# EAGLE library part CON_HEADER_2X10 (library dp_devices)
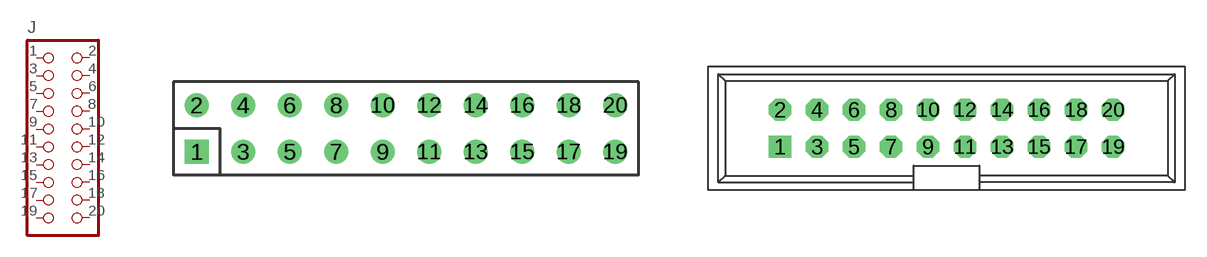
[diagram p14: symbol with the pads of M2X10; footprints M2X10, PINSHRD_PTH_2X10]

Designator prefix J

## CON_HEADER_2X10-PTH  [M2X10]
1  1  pas
2  2  pas
3  3  pas
4  4  pas
5  5  pas
6  6  pas
7  7  pas
8  8  pas
9  9  pas
10  10  pas
11  11  pas
12  12  pas
13  13  pas
14  14  pas
15  15  pas
16  16  pas
17  17  pas
18  18  pas
19  19  pas
20  20  pas

## CON_HEADER_2X10-SHROUDED  [PINSHRD_PTH_2X10]
Pads as for M2X10

## Footprint M2X10 (pad centres in mm)
drill 0.8 square: 1 -11.43,-1.27
drill 0.8 round: 2 -11.43,1.27; 3 -8.89,-1.27; 4 -8.89,1.27; 5 -6.35,-1.27; 6 -6.35,1.27; 7 -3.81,-1.27; 8 -3.81,1.27; 9 -1.27,-1.27; 10 -1.27,1.27; 11 1.27,-1.27; 12 1.27,1.27; 13 3.81,-1.27; 14 3.81,1.27; 15 6.35,-1.27; 16 6.35,1.27; 17 8.89,-1.27; 18 8.89,1.27; 19 11.43,-1.27; 20 11.43,1.27

## Footprint PINSHRD_PTH_2X10 (pad centres in mm)
Shrouded 2x10 pin header 0.1"/2.54mm pitch
drill 1.016 square: 1 -11.43,-1.27
drill 1.016 octagon: 2 -11.43,1.27; 3 -8.89,-1.27; 4 -8.89,1.27; 5 -6.35,-1.27; 6 -6.35,1.27; 7 -3.81,-1.27; 8 -3.81,1.27; 9 -1.27,-1.27; 10 -1.27,1.27; 11 1.27,-1.27; 12 1.27,1.27; 13 3.81,-1.27; 14 3.81,1.27; 15 6.35,-1.27; 16 6.35,1.27; 17 8.89,-1.27; 18 8.89,1.27; 19 11.43,-1.27; 20 11.43,1.27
